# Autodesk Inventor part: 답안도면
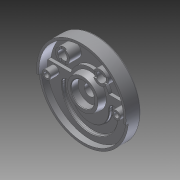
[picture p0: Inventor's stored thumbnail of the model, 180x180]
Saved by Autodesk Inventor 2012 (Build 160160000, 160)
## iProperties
Created: 2015-04
Part Number: 답안도면
Material: Default
Document SubType Name: Modeling
Designer: Owner
Mass: 398.623 g
Surface Area: 1053.09 cm^2
Volume: 398.623 cm^3
Density: 1 g/cm^3
Author: Owner
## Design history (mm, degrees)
sketch "스케치1"
  geometry: C1 r 95 at (0, 0); 1 further point
  constraints: 1 centre point, 1 coincident
  dimensions: "d0" = 190 diameter of C1
extrude "돌출1" new body sketch "스케치1" distance "d1" = 32; taper "d2" = 0 deg
sketch "스케치2"
  geometry: C1 r 95 at (0, 0) reference; C2 r 90 at (0, 0)
  constraints: 1 centre point, 1 coincident
  dimensions: "d3" = 180 diameter of C2
extrude "돌출2" cut sketch "스케치2" distance "d4" = 18; taper "d5" = 0 deg
sketch "스케치3"
  geometry: L1 (90, 14)-(-90, 14) reference; L2 (0, 0)-(0, 65.515); L3 (-35, 14)-(-32.355, 29); L4 (-32.355, 29)-(0, 29); L5 (-35, 14)-(0, 14)
  constraints: 8 end point, 3 point on line, 1 midpoint, 1 parallel, 1 perpendicular
  dimensions: "d6" = 100 deg angle of L1 L3; "d7" = 15 distance between parallel lines of L4 L1; "d8" = 70 diameter of L3.start L2
revolve "회전1" sketch "스케치3" stored, may be unused: angle "d9" = 90 deg
sketch "스케치4"
  geometry: L1 (-89.196, 12)-(-40.249, 12); L2 (40.249, 12)-(89.196, 12); C1 r 35 at (0, 0) reference; A1 r 42 centre (0, 0) between (40.249, 12) and (-40.249, 12); A2 r 90 centre (0, 0) between (89.196, 12) and (-89.196, 12); 2 further points
  constraints: 4 end point, 4 point on circle, 2 centre point, 2 coincident, 2 horizontal, 1 horizontal alignment, 1 vertical alignment, 2 other
  dimensions: "d11" = 84 diameter of A1; "d110" = 12 distance from line of C1.centre L2
extrude "돌출4" cut sketch "스케치4" distance "d15" = 7; taper "d16" = 0 deg
hole "구멍1" diameter "d19" = 23; stored, may be unused: countersink angle "d23" = 90 deg, drill point angle "d25" = 118 deg; dims "d17" = 10, "d18" = 10, "d20" = 6, "d21" = 50, "d22" = 15, "d24" = 8
sketch "스케치5"
  geometry: L1 (89.658, -7.844)-(94.638, -8.28); L2 (-89.658, -7.844)-(-94.638, -8.28); L3 (-89.658, -7.844)-(0, 0); L4 (0, 0)-(89.658, -7.844); L5 (-40.249, 12)-(-89.196, 12) reference; L6 (89.196, 12)-(40.249, 12) reference; A1 r 90 centre (0, 0) between (-89.658, -7.844) and (89.658, -7.844) reference; A2 r 95 centre (0, 0) between (94.638, -8.28) and (-94.638, -8.28) reference
  constraints: 8 end point, 4 point on circle, 2 collinear
  dimensions: "d111" = 5 deg angle of L3 L5; "d112" = 5 deg angle of L4 L6
extrude "돌출5" cut sketch "스케치5" distance "d29" = 5; taper "d30" = 0 deg
sketch "스케치6"
  geometry: L1 (-99.192, -19)-(99.192, -19); L2 (-99.192, -14)-(99.192, -14); L3 (41, -19)-(41, -14); L4 (59, -19)-(59, -14); L5 (-41, -19)-(-41, -14); L6 (-59, -19)-(-59, -14); A1 r 90 centre (0, 0) between (-89.196, 12) and (89.196, 12) reference; A2 r 9 centre (50, -14) between (59, -14) and (41, -14); A3 r 9 centre (-50, -14) between (-41, -14) and (-59, -14); A4 r 59 centre (0, -19) between (-59, -19) and (59, -19); A5 r 41 centre (0, -19) between (-41, -19) and (41, -19); 3 further points
  constraints: 12 end point, 8 point on circle, 7 point on line, 6 parallel, 5 tangent, 4 centre point, 2 coincident, 2 midpoint, 2 vertical alignment, 1 equal radius, 1 perpendicular
  dimensions: "d45" = 5 distance between parallel lines of L1 L2; "d47" = 18 distance between parallel lines of L4 L3; "d48" = 41 radius of A5; "d113" = 19 distance from line of L1 A1.centre
extrude "돌출6" cut sketch "스케치6" distance "d49" = 7; taper "d50" = 0 deg
sketch "스케치8"
  geometry: C1 r 11.5 at (0, 0) reference; C2 r 9 at (74, 0)
  constraints: 1 centre point, 1 horizontal alignment
  dimensions: "d53" = 18 diameter of C2; "d54" = 74 distance of C2.centre C1.centre
extrude "돌출7" join sketch "스케치8" stored distance "d55" = 7; taper "d56" = 0 deg
sketch "스케치9"
  geometry: C1 r 11.5 at (0, 0) reference; 1 further point
  constraints: 1 horizontal alignment
  dimensions: "d57" = 74 distance of point (74, 0) C1.centre
hole "구멍2" sketch "스케치9" at (74, 0) diameter "d58" = 11; stored, may be unused: countersink angle "d62" = 90 deg, drill point angle "d64" = 118 deg; dims "d59" = 6, "d60" = 18, "d61" = 11, "d63" = 8
sketch "스케치10"
  geometry: C1 r 11.5 at (0, 0) reference; C2 r 15 at (-40, 52)
  constraints: 1 centre point
  dimensions: "d65" = 30 diameter of C2; "d66" = 52 vertical distance of C1.centre C2.centre; "d67" = 40 horizontal distance of C1.centre C2.centre
extrude "돌출8" join sketch "스케치10" stored distance "d68" = 7; taper "d69" = 0 deg
hole "구멍3" diameter "d72" = 20; stored, may be unused: countersink angle "d76" = 90 deg, drill point angle "d78" = 118 deg; dims "d70" = 10, "d71" = 10, "d73" = 6, "d74" = 18, "d75" = 11, "d77" = 8
sketch "스케치11"
  geometry: L1 (-6, 13.748)-(-6, 8); L2 (-6, -8)-(-6, -13.748); L3 (6, 13.748)-(6, 8); L4 (6, -8)-(6, -13.748); A1 r 10 centre (0, 0) between (-6, 8) and (-6, -8) reference; A2 r 15 centre (0, 0) between (-6, 13.748) and (-6, -13.748) reference; 1 further point
  constraints: 8 end point, 8 point on circle, 6 parallel, 2 vertical
  dimensions: "d80" = 12 distance between parallel lines of L3 L1; "d81" = 12 distance between parallel lines of L4 L2
extrude "돌출9" cut sketch "스케치11" distance "d82" = 3; taper "d83" = 0 deg
sketch "스케치12"
  geometry: L1 (-13.748, 6)-(-8, 6); L2 (8, 6)-(13.748, 6); L3 (-13.748, -6)-(-8, -6); L4 (8, -6)-(13.748, -6); A1 r 10 centre (0, 0) between (-8, 6) and (8, 6) reference; A2 r 15 centre (0, 0) between (-13.748, -6) and (13.748, -6) reference; 1 further point
  constraints: 8 end point, 8 point on circle, 6 parallel, 2 horizontal
  dimensions: "d84" = 12 distance between parallel lines of L3 L1; "d85" = 12 distance between parallel lines of L4 L2
extrude "돌출10" cut sketch "스케치12" distance "d86" = 3; taper "d87" = 0 deg
sketch "스케치13"
  geometry: L1 (36.062, -36.062)-(50.912, -50.912); L2 (-36.062, -36.062)-(-50.912, -50.912); L3 (-36.062, -36.062)-(0, 0); L4 (0, 0)-(36.062, -36.062); C1 r 11.5 at (0, 0) reference; C2 r 95 at (0, 0) reference; A1 r 51 centre (0, 0) between (-36.062, -36.062) and (36.062, -36.062); A2 r 72 centre (0, 0) between (-50.912, -50.912) and (50.912, -50.912); 1 further point
  constraints: 8 end point, 5 point on circle, 3 coincident, 2 centre point, 1 collinear, 1 perpendicular, 1 vertical alignment
  dimensions: "d91" = 90 deg angle of L1 L2; "d92" = 72 radius of A2; "d93" = 51 radius of A1
extrude "돌출11" join sketch "스케치13" distance "d94" = 5; taper "d95" = 0 deg
fillet "모깎기1" dims "d98" = 5
chamfer "모따기1" distance "d101" = 1; stored, may be unused: second distance "d102" = 2, angle "d103" = 45 deg
fillet "모깎기4" dims "d104" = 3
fillet "모깎기5" dims "d105" = 5
fillet "모깎기6" dims "d106" = 1
node "솔리드1"
mirror "대칭1"
mirror "대칭2"
other parameters: "d10" = 12, "d32" = 118, "d33" = 19, "d43" = 82, "d44" = 118, "d79" = 12, "d89" = 144, "d90" = 90 deg, "d109" = 12
